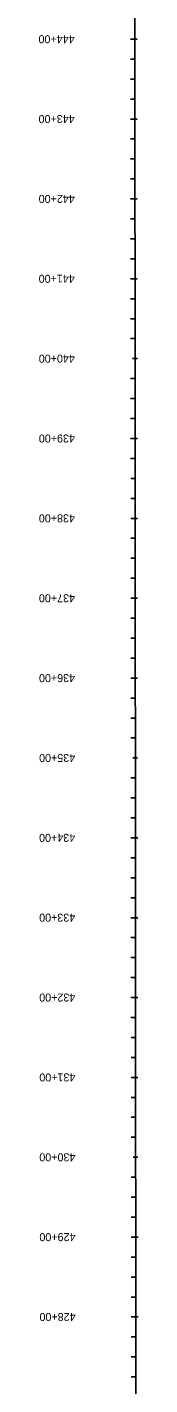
# Model space of a CAD drawing. Extents: x 23417911 to 23421158, y 6737892 to 6791804.
# Drawn here: x 23420711 to 23420835, y 6768213 to 6769913 of the extents above; entities that cross this region are included whole.
import ezdxf

# ---------------------------------------------------------------- set-up
doc = ezdxf.new("R2010")
doc.units = 0
for name, color, linetype in [('Alignment', 7, 'Continuous'), ('TextAlignmentLrg', 7, 'Continuous'), ('TextAlignmentSml', 7, 'Continuous')]:
    doc.layers.add(name, color=color, linetype=linetype)

msp = doc.modelspace()

# ---------------------------------------------------------------- linework, layer by layer
at = {"layer": 'Alignment'}
msp.add_line((23420834.6, 6764732), (23420829.5, 6771769.1), dxfattribs=at)
msp.add_line((23420834.6, 6764732), (23420829.5, 6771769.1), dxfattribs=at)
at = {"layer": 'TextAlignmentLrg'}
for p, q in [((23420830.8, 6769897.6), (23420825.4, 6769897.6)), ((23420830.9, 6769797.6), (23420825.4, 6769797.6)), ((23420831, 6769697.6), (23420825.5, 6769697.6)), ((23420831, 6769597.6), (23420825.6, 6769597.6)), ((23420828, 6769497.6), (23420834.2, 6769497.6)), ((23420831.2, 6769397.6), (23420825.7, 6769397.6)), ((23420831.2, 6769297.6), (23420825.8, 6769297.6)), ((23420831.3, 6769197.6), (23420825.9, 6769197.6)), ((23420831.4, 6769097.6), (23420825.9, 6769097.6)), ((23420828.4, 6768997.6), (23420834.5, 6768997.6)), ((23420831.5, 6768897.6), (23420826.1, 6768897.6)), ((23420831.6, 6768797.6), (23420826.2, 6768797.6)), ((23420831.7, 6768697.6), (23420826.2, 6768697.6)), ((23420831.8, 6768597.6), (23420826.3, 6768597.6)), ((23420828.8, 6768497.6), (23420834.9, 6768497.6)), ((23420831.9, 6768397.6), (23420826.4, 6768397.6)), ((23420832, 6768297.6), (23420826.5, 6768297.6))]:
    msp.add_line(p, q, dxfattribs=at)
at = {"layer": 'TextAlignmentSml'}
for p, q in [((23420827.8, 6769897.6), (23420833.9, 6769897.6)), ((23420830.8, 6769872.6), (23420825.4, 6769872.6)), ((23420830.8, 6769847.6), (23420825.4, 6769847.6)), ((23420830.9, 6769822.6), (23420825.4, 6769822.6)), ((23420827.8, 6769797.6), (23420833.9, 6769797.6)), ((23420830.9, 6769772.6), (23420825.4, 6769772.6)), ((23420830.9, 6769747.6), (23420825.5, 6769747.6)), ((23420830.9, 6769722.6), (23420825.5, 6769722.6)), ((23420827.9, 6769697.6), (23420834, 6769697.6)), ((23420831, 6769672.6), (23420825.5, 6769672.6)), ((23420831, 6769647.6), (23420825.5, 6769647.6)), ((23420831, 6769622.6), (23420825.6, 6769622.6)), ((23420828, 6769597.6), (23420834.1, 6769597.6)), ((23420831, 6769572.6), (23420825.6, 6769572.6)), ((23420831.1, 6769547.6), (23420825.6, 6769547.6)), ((23420831.1, 6769522.6), (23420825.6, 6769522.6)), ((23420828, 6769497.6), (23420834.2, 6769497.6)), ((23420831.1, 6769472.6), (23420825.7, 6769472.6)), ((23420831.1, 6769447.6), (23420825.7, 6769447.6)), ((23420831.2, 6769422.6), (23420825.7, 6769422.6)), ((23420828.1, 6769397.6), (23420834.2, 6769397.6)), ((23420831.2, 6769372.6), (23420825.7, 6769372.6)), ((23420831.2, 6769347.6), (23420825.8, 6769347.6)), ((23420831.2, 6769322.6), (23420825.8, 6769322.6)), ((23420828.2, 6769297.6), (23420834.3, 6769297.6)), ((23420831.3, 6769272.6), (23420825.8, 6769272.6)), ((23420831.3, 6769247.6), (23420825.8, 6769247.6)), ((23420831.3, 6769222.6), (23420825.8, 6769222.6)), ((23420828.3, 6769197.6), (23420834.4, 6769197.6)), ((23420831.3, 6769172.6), (23420825.9, 6769172.6)), ((23420831.4, 6769147.6), (23420825.9, 6769147.6)), ((23420831.4, 6769122.6), (23420825.9, 6769122.6)), ((23420828.3, 6769097.6), (23420834.5, 6769097.6)), ((23420831.4, 6769072.6), (23420826, 6769072.6)), ((23420831.4, 6769047.6), (23420826, 6769047.6)), ((23420831.4, 6769022.6), (23420826, 6769022.6)), ((23420828.4, 6768997.6), (23420834.5, 6768997.6)), ((23420831.5, 6768972.6), (23420826, 6768972.6)), ((23420831.5, 6768947.6), (23420826, 6768947.6)), ((23420831.5, 6768922.6), (23420826.1, 6768922.6)), ((23420828.5, 6768897.6), (23420834.6, 6768897.6)), ((23420831.6, 6768872.6), (23420826.1, 6768872.6)), ((23420831.6, 6768847.6), (23420826.1, 6768847.6)), ((23420831.6, 6768822.6), (23420826.1, 6768822.6)), ((23420828.6, 6768797.6), (23420834.7, 6768797.6)), ((23420831.6, 6768772.6), (23420826.2, 6768772.6)), ((23420831.6, 6768747.6), (23420826.2, 6768747.6)), ((23420831.7, 6768722.6), (23420826.2, 6768722.6)), ((23420828.6, 6768697.6), (23420834.7, 6768697.6)), ((23420831.7, 6768672.6), (23420826.2, 6768672.6)), ((23420831.7, 6768647.6), (23420826.3, 6768647.6)), ((23420831.7, 6768622.6), (23420826.3, 6768622.6)), ((23420828.7, 6768597.6), (23420834.8, 6768597.6)), ((23420831.8, 6768572.6), (23420826.3, 6768572.6)), ((23420831.8, 6768547.6), (23420826.3, 6768547.6)), ((23420831.8, 6768522.6), (23420826.4, 6768522.6)), ((23420828.8, 6768497.6), (23420834.9, 6768497.6)), ((23420831.8, 6768472.6), (23420826.4, 6768472.6)), ((23420831.9, 6768447.6), (23420826.4, 6768447.6)), ((23420831.9, 6768422.6), (23420826.4, 6768422.6)), ((23420828.8, 6768397.6), (23420835, 6768397.6)), ((23420831.9, 6768372.6), (23420826.5, 6768372.6)), ((23420831.9, 6768347.6), (23420826.5, 6768347.6)), ((23420832, 6768322.6), (23420826.5, 6768322.6)), ((23420828.9, 6768297.6), (23420835, 6768297.6)), ((23420832, 6768272.6), (23420826.5, 6768272.6)), ((23420832, 6768247.6), (23420826.6, 6768247.6)), ((23420832, 6768222.6), (23420826.6, 6768222.6))]:
    msp.add_line(p, q, dxfattribs=at)

# ---------------------------------------------------------------- texts
at = {"layer": 'TextAlignmentLrg'}
for s, p in [('440+00', (23420756.1, 6769502.6)), ('435+00', (23420756.5, 6769002.6)), ('430+00', (23420756.8, 6768502.6))]:
    msp.add_text(s, height=10.02, rotation=180.0416, dxfattribs=at).set_placement(p)
at = {"layer": 'TextAlignmentSml'}
for s, p in [('444+00', (23420755.8, 6769902.6)), ('443+00', (23420755.9, 6769802.6)), ('442+00', (23420756, 6769702.6)), ('441+00', (23420756, 6769602.6)), ('440+00', (23420756.1, 6769502.6)), ('439+00', (23420756.2, 6769402.6)), ('438+00', (23420756.2, 6769302.6)), ('437+00', (23420756.3, 6769202.6)), ('436+00', (23420756.4, 6769102.6)), ('435+00', (23420756.5, 6769002.6)), ('434+00', (23420756.5, 6768902.6)), ('433+00', (23420756.6, 6768802.6)), ('432+00', (23420756.7, 6768702.6)), ('431+00', (23420756.8, 6768602.6)), ('430+00', (23420756.8, 6768502.6)), ('429+00', (23420756.9, 6768402.6)), ('428+00', (23420757, 6768302.6))]:
    msp.add_text(s, height=10.02, rotation=180.0416, dxfattribs=at).set_placement(p)

doc.saveas('drawing.dxf')
